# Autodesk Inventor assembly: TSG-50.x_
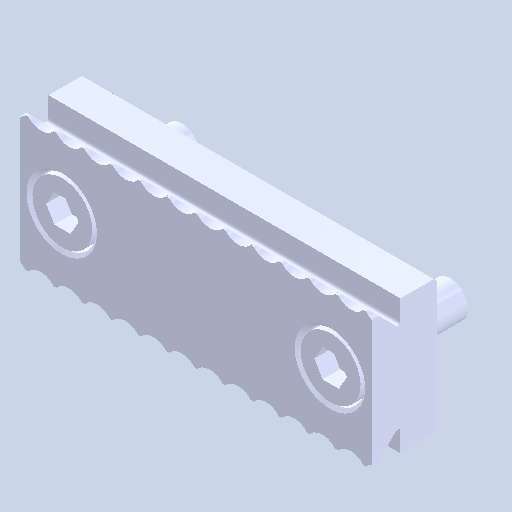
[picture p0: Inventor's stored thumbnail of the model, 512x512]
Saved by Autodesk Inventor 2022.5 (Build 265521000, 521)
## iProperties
Created: 2024-05
Part Number: TSG-50.x_
Document SubType Name: Assembly
Designer: ImaoCorp
Author: ImaoCorp
Sending System: SOLIDWORKS 2022-2022290
MC: AMD64
MC_MODEL: Intel64 Family 6 Model 60 Stepping 3, GenuineIntel
OS: Windows_NT
FRU: Parasolid Version 33.1, build 260,  4-25-2022
FORMAT: text
GUISE: transmit
KEY: FILETSG-50.x_t
DATE: Mon May 20 16:28:17 2024
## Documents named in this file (4)
- X:\14_SW2022-Inv2022\保留中\mitee-bite\データ\tsg-50\TSG-50.x_.iam
- X:\14_SW2022-Inv2022\保留中\mitee-bite\データ\tsg-50\TSG-50_01.ipt
- X:\14_SW2022-Inv2022\保留中\mitee-bite\データ\tsg-50\TSG-50_02.ipt
- X:\14_SW2022-Inv2022\保留中\mitee-bite\データ\tsg-50\TSG-50_03.ipt
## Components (3 placed, 3 different names)
1. TSG-50_01
2. TSG-50_02
3. TSG-50_03
